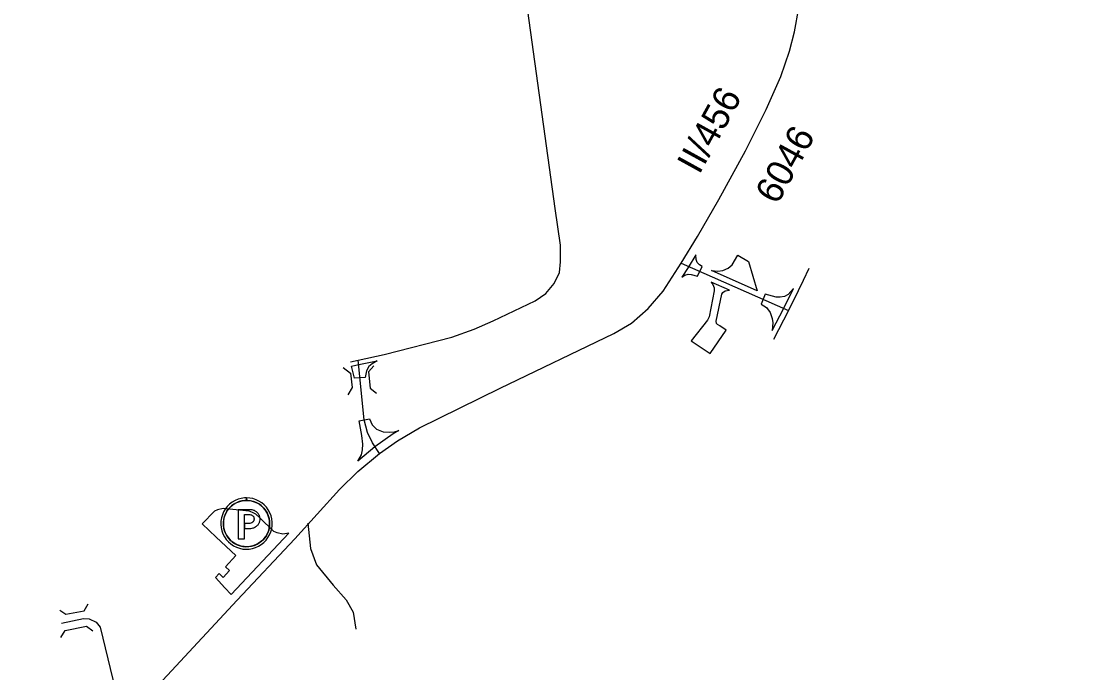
# Model space of a CAD drawing. Extents: x -546703 to -534152, y -1046534 to -1035676.
# Drawn here: x -542892.6 to -542498, y -1040049.1 to -1039805.7 of the extents above; entities that cross this region are included whole.
import ezdxf

# ---------------------------------------------------------------- set-up
doc = ezdxf.new("R2010")
doc.units = 0
for name, color, linetype in [('Vrstva 19', 7, 'Continuous'), ('Vrstva 22', 7, 'Continuous'), ('Vrstva 26', 7, 'Continuous'), ('Vrstva 3', 7, 'Continuous'), ('Vrstva 46', 7, 'Continuous'), ('Vrstva 7', 7, 'Continuous'), ('Vrstva 8', 7, 'Continuous')]:
    doc.layers.add(name, color=color, linetype=linetype)

msp = doc.modelspace()

# ---------------------------------------------------------------- linework, layer by layer
at = {"layer": 'Vrstva 19'}
for points in [[(-542634.6, -1039898.84), (-542632.27, -1039899.1), (-542630.31, -1039898.79), (-542628.41, -1039898), (-542626.9, -1039896.67), (-542624.78, -1039893.13), (-542620.78, -1039895.41), (-542617.55, -1039906.38)], [(-542635.09, -1039929.76), (-542629.13, -1039921.16), (-542631.5, -1039919.49), (-542632.34, -1039918.96), (-542632.68, -1039918.57), (-542632.84, -1039917.69), (-542630.74, -1039907.67), (-542630.3, -1039907.01), (-542629.47, -1039906.4), (-542627.8, -1039906.22), (-542634.69, -1039903.18), (-542634.06, -1039904.08), (-542633.56, -1039905.35), (-542633.62, -1039906.46), (-542635.44, -1039916.08), (-542636.11, -1039917.36), (-542642.13, -1039925.1)], [(-542824.97, -1039993.4), (-542819.66, -1039998.37), (-542812.31, -1040005.26), (-542816.2, -1040009.44), (-542814.67, -1040010.86), (-542817.1, -1040013.47), (-542818.63, -1040012.05), (-542819.99, -1040013.51), (-542816.52, -1040017.35), (-542814.03, -1040019.89), (-542792.56, -1039996.95), (-542794.8, -1039997.34), (-542796.84, -1039996.85), (-542798.19, -1039996.27), (-542803.4, -1039991.15), (-542804.84, -1039989.82), (-542806.11, -1039989.16), (-542807.33, -1039988.72), (-542817.06, -1039987.67), (-542819.16, -1039988.16), (-542820.33, -1039988.72)]]:
    msp.add_lwpolyline(points, close=True, dxfattribs=at)
at = {"layer": 'Vrstva 22'}
msp.add_lwpolyline([(-542851.04, -1040064.16), (-542811.84, -1040021.93), (-542790.35, -1039998.98), (-542773.61, -1039980.58), (-542766.74, -1039973.9), (-542758.61, -1039967.12), (-542751.93, -1039962.38), (-542743.71, -1039957.54), (-542713.61, -1039942.82), (-542671.12, -1039922.39), (-542664.54, -1039918.51), (-542658.25, -1039912.99), (-542652.64, -1039906.5), (-542645.86, -1039896.05), (-542639.86, -1039886.17), (-542631.83, -1039872.32), (-542621.86, -1039854.12), (-542614.12, -1039838.72), (-542608.7, -1039826.33), (-542605.41, -1039816.93), (-542603.57, -1039809.67), (-542601.93, -1039800.76)], dxfattribs=at)
at = {"layer": 'Vrstva 26'}
msp.add_arc((-542604.39, -1039692.44), 500, 284.3744, 180.9424, dxfattribs=at)
at = {"layer": 'Vrstva 3'}
msp.add_lwpolyline([(-542851.04, -1040064.16), (-542811.84, -1040021.93), (-542790.35, -1039998.98), (-542773.61, -1039980.58), (-542766.74, -1039973.9), (-542758.61, -1039967.12), (-542751.93, -1039962.38), (-542743.71, -1039957.54), (-542713.61, -1039942.82), (-542671.12, -1039922.39), (-542664.54, -1039918.51), (-542658.25, -1039912.99), (-542652.64, -1039906.5), (-542645.86, -1039896.05), (-542639.86, -1039886.17), (-542631.83, -1039872.32), (-542621.86, -1039854.12), (-542614.12, -1039838.72), (-542608.7, -1039826.33), (-542605.41, -1039816.93), (-542603.57, -1039809.67), (-542601.93, -1039800.76)], dxfattribs=at)
at = {"layer": 'Vrstva 46'}
for points in [[(-542808.37, -1039983.73), (-542809.16, -1039983.76), (-542810.37, -1039983.94), (-542811.53, -1039984.27), (-542812.65, -1039984.74), (-542813.7, -1039985.35), (-542814.67, -1039986.09), (-542815.53, -1039986.95), (-542816.28, -1039987.9), (-542816.9, -1039988.94), (-542817.39, -1039990.06), (-542817.73, -1039991.22), (-542817.92, -1039992.42), (-542817.96, -1039993.63), (-542817.85, -1039994.84), (-542817.58, -1039996.03), (-542817.17, -1039997.17), (-542816.61, -1039998.25), (-542815.93, -1039999.25), (-542815.12, -1040000.16), (-542814.21, -1040000.96), (-542813.2, -1040001.64), (-542812.11, -1040002.18), (-542810.97, -1040002.58), (-542809.78, -1040002.84), (-542808.57, -1040002.94), (-542807.36, -1040002.89), (-542806.16, -1040002.69), (-542805, -1040002.33), (-542803.89, -1040001.84), (-542802.85, -1040001.21), (-542801.9, -1040000.45), (-542801.06, -1039999.58), (-542800.33, -1039998.6), (-542799.73, -1039997.55), (-542799.27, -1039996.43), (-542798.95, -1039995.25), (-542798.78, -1039994.05), (-542798.77, -1039992.84), (-542798.91, -1039991.63), (-542799.2, -1039990.45), (-542799.64, -1039989.32), (-542800.21, -1039988.25), (-542800.92, -1039987.26), (-542801.75, -1039986.37), (-542802.68, -1039985.59), (-542803.7, -1039984.94), (-542804.8, -1039984.42), (-542805.95, -1039984.04), (-542807.15, -1039983.81), (-542808.36, -1039983.73)], [(-542799.71, -1039993.34), (-542799.78, -1039992.25), (-542799.99, -1039991.17), (-542800.33, -1039990.13), (-542800.8, -1039989.15), (-542801.39, -1039988.23), (-542802.09, -1039987.39), (-542802.89, -1039986.64), (-542803.78, -1039986.01), (-542804.74, -1039985.49), (-542805.76, -1039985.09), (-542806.82, -1039984.83), (-542807.91, -1039984.7), (-542809, -1039984.71), (-542810.08, -1039984.86), (-542811.14, -1039985.15), (-542812.15, -1039985.56), (-542813.1, -1039986.1), (-542813.97, -1039986.76), (-542814.76, -1039987.52), (-542815.44, -1039988.37), (-542816.01, -1039989.31), (-542816.46, -1039990.31), (-542816.78, -1039991.35), (-542816.96, -1039992.43), (-542817.01, -1039993.52), (-542816.91, -1039994.61), (-542816.68, -1039995.68), (-542816.32, -1039996.71), (-542815.83, -1039997.69), (-542815.22, -1039998.6), (-542814.51, -1039999.42), (-542813.69, -1040000.15), (-542812.79, -1040000.76), (-542811.82, -1040001.26), (-542810.79, -1040001.64), (-542809.72, -1040001.88), (-542808.63, -1040001.98), (-542807.54, -1040001.94), (-542806.46, -1040001.77), (-542805.41, -1040001.47), (-542804.41, -1040001.03), (-542803.47, -1040000.47), (-542802.61, -1039999.79), (-542801.84, -1039999.02), (-542801.18, -1039998.15), (-542800.63, -1039997.2), (-542800.2, -1039996.2), (-542799.91, -1039995.14), (-542799.75, -1039994.06), (-542799.71, -1039993.34)], [(-542808.36, -1039984.69), (-542807.64, -1039984.72), (-542806.56, -1039984.88), (-542805.51, -1039985.18), (-542804.5, -1039985.6), (-542803.55, -1039986.15), (-542802.69, -1039986.81), (-542801.91, -1039987.58), (-542801.23, -1039988.44), (-542800.67, -1039989.38), (-542800.23, -1039990.38), (-542799.93, -1039991.43), (-542799.75, -1039992.51), (-542799.72, -1039993.61), (-542799.82, -1039994.69), (-542800.06, -1039995.76), (-542800.43, -1039996.79), (-542800.93, -1039997.76), (-542801.55, -1039998.66), (-542802.28, -1039999.48), (-542803.1, -1040000.2), (-542804.01, -1040000.81), (-542804.98, -1040001.3), (-542806.02, -1040001.66), (-542807.08, -1040001.89), (-542808.17, -1040001.98), (-542809.27, -1040001.94), (-542810.34, -1040001.75), (-542811.39, -1040001.44), (-542812.39, -1040000.99), (-542813.32, -1040000.42), (-542814.17, -1039999.74), (-542814.94, -1039998.95), (-542815.59, -1039998.08), (-542816.13, -1039997.13), (-542816.55, -1039996.12), (-542816.83, -1039995.06), (-542816.98, -1039993.98), (-542817, -1039992.89), (-542816.87, -1039991.8), (-542816.61, -1039990.74), (-542816.21, -1039989.72), (-542815.69, -1039988.76), (-542815.06, -1039987.87), (-542814.31, -1039987.07), (-542813.48, -1039986.37), (-542812.56, -1039985.78), (-542811.57, -1039985.31), (-542810.53, -1039984.97), (-542809.46, -1039984.76), (-542808.37, -1039984.69)], [(-542808.37, -1039984.69), (-542808.37, -1039983.73)], [(-542808.36, -1039983.73), (-542808.36, -1039984.69)], [(-542806.78, -1039988.15), (-542811.47, -1039988.15), (-542811.47, -1039998.98), (-542809.17, -1039998.98), (-542809.17, -1039993.27)], [(-542809.17, -1039993.27), (-542809.17, -1039989.95)], [(-542809.17, -1039989.95), (-542807.3, -1039989.95)], [(-542807.3, -1039989.95), (-542807.21, -1039989.95), (-542807.12, -1039989.95), (-542806.7, -1039990.03), (-542806.53, -1039990.12), (-542806.36, -1039990.2), (-542806.19, -1039990.29), (-542806.02, -1039990.46), (-542805.85, -1039990.63), (-542805.68, -1039990.88), (-542805.59, -1039991.14), (-542805.51, -1039991.57), (-542805.51, -1039991.74), (-542805.59, -1039992.08), (-542805.68, -1039992.33), (-542805.85, -1039992.59), (-542805.93, -1039992.67), (-542806.1, -1039992.85), (-542806.36, -1039993.02), (-542806.53, -1039993.1), (-542806.78, -1039993.19), (-542807.12, -1039993.27), (-542807.3, -1039993.27)], [(-542806.78, -1039995.15), (-542806.27, -1039995.06), (-542805.93, -1039994.98), (-542805.68, -1039994.89), (-542805.42, -1039994.81), (-542805.25, -1039994.72), (-542805.08, -1039994.64), (-542804.82, -1039994.47), (-542804.57, -1039994.29), (-542804.4, -1039994.12), (-542804.23, -1039993.95), (-542804.05, -1039993.78), (-542803.88, -1039993.53), (-542803.71, -1039993.27), (-542803.63, -1039993.1), (-542803.54, -1039992.93), (-542803.46, -1039992.67), (-542803.37, -1039992.42), (-542803.29, -1039991.99), (-542803.29, -1039991.74), (-542803.29, -1039991.4), (-542803.37, -1039990.97), (-542803.37, -1039990.88), (-542803.46, -1039990.63), (-542803.54, -1039990.37), (-542803.71, -1039990.03), (-542803.88, -1039989.78), (-542804.05, -1039989.52), (-542804.23, -1039989.35), (-542804.4, -1039989.18), (-542804.57, -1039989.01), (-542804.82, -1039988.84), (-542805.08, -1039988.67), (-542805.25, -1039988.58), (-542805.42, -1039988.5), (-542805.68, -1039988.41), (-542805.85, -1039988.33), (-542806.27, -1039988.24), (-542806.78, -1039988.15)], [(-542807.3, -1039993.27), (-542809.13, -1039993.27)], [(-542809.13, -1039993.27), (-542809.13, -1039995.15)], [(-542809.13, -1039995.15), (-542806.78, -1039995.15)]]:
    msp.add_lwpolyline(points, dxfattribs=at)
at = {"layer": 'Vrstva 7'}
msp.add_line((-542645.86, -1039896.05), (-542605.78, -1039913.77), dxfattribs=at)
for points in [[(-542769.45, -1039932.88), (-542766.69, -1039932.28), (-542756.86, -1039930.15), (-542731.6, -1039923.76), (-542723.28, -1039920.76), (-542716.12, -1039917.66), (-542700.44, -1039910.2), (-542696.47, -1039907.39), (-542693.38, -1039903.62), (-542691.44, -1039899.55), (-542690.96, -1039895.58), (-542691.05, -1039889.4), (-542692.99, -1039875.63), (-542703.25, -1039801.84), (-542705.67, -1039782.09), (-542711.28, -1039727.38), (-542714.96, -1039690.77), (-542718.71, -1039653.17)], [(-542598.2, -1039898.11), (-542600.35, -1039902.6), (-542602.18, -1039906.41), (-542605.78, -1039913.77), (-542611.43, -1039924.54)], [(-542758.61, -1039967.12), (-542761.22, -1039963.15), (-542763.16, -1039959.28), (-542764.34, -1039954.6), (-542766.69, -1039932.28)], [(-542785.5, -1039993.2), (-542784.39, -1040002.68), (-542782.17, -1040008.73), (-542775.92, -1040016.39), (-542771.08, -1040021.84), (-542768.45, -1040026.47), (-542767.45, -1040032.73)], [(-542877.56, -1040030.5), (-542869.34, -1040028.85), (-542867.21, -1040028.95), (-542864.5, -1040030.11), (-542863.05, -1040032.05), (-542858.31, -1040051.61), (-542856.66, -1040055.97), (-542855.11, -1040058.97), (-542851.04, -1040064.16)]]:
    msp.add_lwpolyline(points, dxfattribs=at)
for points in [[(-542643.32, -1039897.64), (-542645.7, -1039901.32), (-542644.59, -1039900.62), (-542643.33, -1039900.24), (-542642.19, -1039900.27), (-542639.81, -1039900.91), (-542638.06, -1039897.31), (-542639.1, -1039896.7), (-542639.98, -1039895.78), (-542640.33, -1039894.77), (-542640.45, -1039892.91)], [(-542603.98, -1039905.54), (-542605.93, -1039907.73), (-542607.28, -1039908.54), (-542608.9, -1039908.84), (-542610.42, -1039908.81), (-542614.57, -1039907.7), (-542616.04, -1039911.42), (-542614, -1039912.7), (-542612.61, -1039914.56), (-542611.89, -1039916.78), (-542611.69, -1039918.36), (-542611.94, -1039921.21), (-542607.56, -1039912.87)], [(-542759.48, -1039932.51), (-542761.43, -1039933.62), (-542762.6, -1039934.7), (-542763.46, -1039936.24), (-542763.74, -1039937.48), (-542763.99, -1039938.77), (-542767.99, -1039939.03), (-542769.08, -1039934.59), (-542766.32, -1039933.99)], [(-542762.37, -1039954.25), (-542761.37, -1039956.48), (-542759.79, -1039958.09), (-542757.26, -1039959.14), (-542755.05, -1039959.26), (-542753, -1039959.14), (-542751.44, -1039958.61), (-542753.56, -1039959.86), (-542760.44, -1039964.74), (-542766.76, -1039970.01), (-542765.38, -1039967.71), (-542764.97, -1039965.84), (-542764.94, -1039963.69), (-542765.29, -1039960.5), (-542766.31, -1039954.95)]]:
    msp.add_lwpolyline(points, close=True, dxfattribs=at)
at = {"layer": 'Vrstva 8'}
for points in [[(-542772.23, -1039935), (-542769.52, -1039937.15), (-542768.93, -1039942.5), (-542770.53, -1039945.29)], [(-542760.8, -1039934.42), (-542762.8, -1039936.73), (-542762.13, -1039942.82), (-542759.74, -1039944.66)], [(-542878.12, -1040025.67), (-542875.89, -1040027.12), (-542869.05, -1040025.95), (-542867.5, -1040023.33)], [(-542877.78, -1040035.95), (-542876.13, -1040033.24), (-542868.18, -1040031.66), (-542865.76, -1040033.41)]]:
    msp.add_lwpolyline(points, dxfattribs=at)

# ---------------------------------------------------------------- texts
at = {"layer": 'Vrstva 22'}
msp.add_text('6046', height=10, rotation=61.1652, dxfattribs=at).set_placement((-542609.98, -1039874.58))
at = {"layer": 'Vrstva 3'}
msp.add_text('II/456', height=10, rotation=61.1652, dxfattribs=at).set_placement((-542639.17, -1039863.29))

doc.saveas('drawing.dxf')
